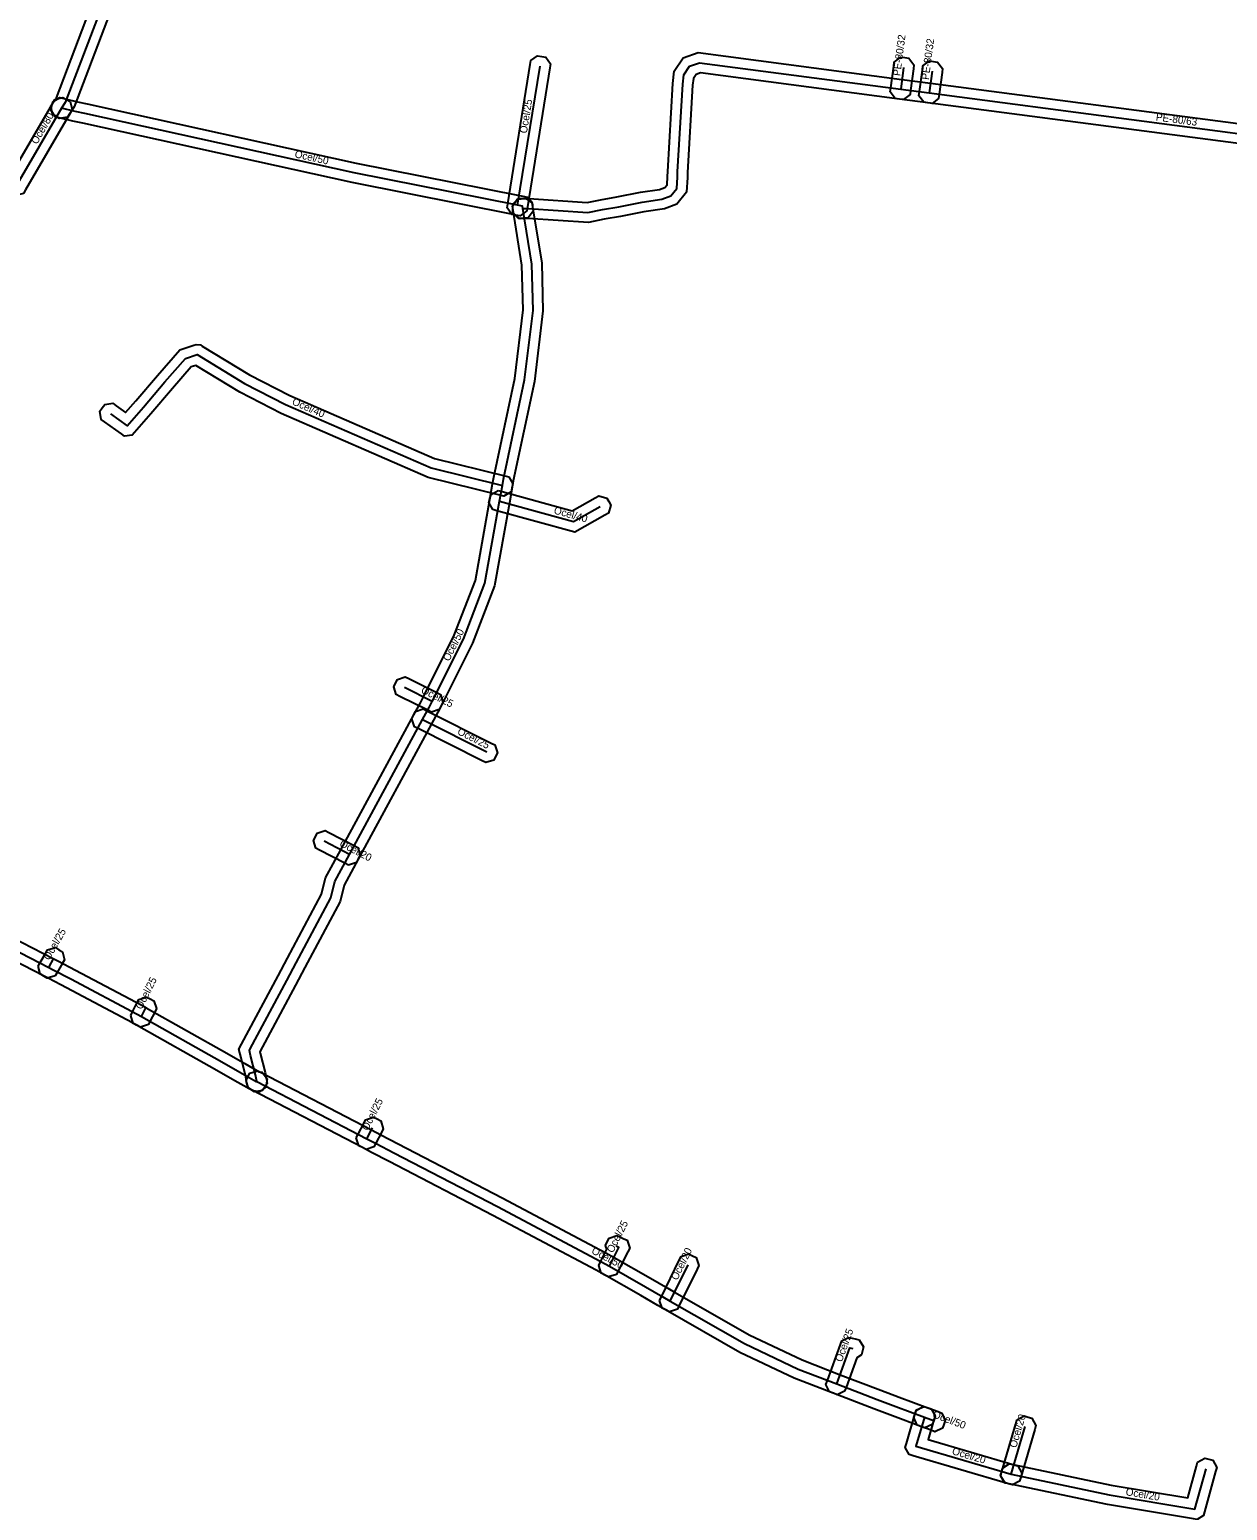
# Model space of a CAD drawing. Extents: x -569373 to -565022, y -1135090 to -1131496.
# Drawn here: x -565419.4 to -565298.7, y -1134134.8 to -1133985.7 of the extents above; entities that cross this region are included whole.
import ezdxf

# ---------------------------------------------------------------- set-up
doc = ezdxf.new("R2010")
doc.units = 0
for name, color, linetype in [('1', 7, 'Continuous'), ('24', 7, 'Continuous'), ('30', 7, 'Continuous')]:
    doc.layers.add(name, color=color, linetype=linetype)

msp = doc.modelspace()

# ---------------------------------------------------------------- linework, layer by layer
at = {"layer": '1'}
for points in [[(-565408.608, -1133977.01), (-565414.865, -1133993.461), (-565415.308, -1133994.125), (-565415.538, -1133994.47), (-565416.35, -1133994.632), (-565416.695, -1133994.402), (-565417.04, -1133994.172), (-565417.202, -1133993.36), (-565416.972, -1133993.015), (-565416.655, -1133992.539), (-565410.452, -1133976.23)], [(-565288.17, -1133998.391), (-565328.891, -1133993.041), (-565331.77, -1133992.661), (-565351.801, -1133990.033), (-565352.249, -1133990.193), (-565352.515, -1133990.581), (-565352.593, -1133991.266), (-565353.101, -1134000.048), (-565353.121, -1134000.57), (-565353.211, -1134002.05), (-565354.174, -1134003.241), (-565355.439, -1134003.714), (-565357.49, -1134004.016), (-565359.846, -1134004.483), (-565361.482, -1134004.772), (-565363.061, -1134005.097), (-565369.172, -1134004.689), (-565369.708, -1134004.68), (-565370.122, -1134004.673), (-565370.697, -1134004.076), (-565370.69, -1134003.662), (-565370.683, -1134003.248), (-565370.086, -1134002.673), (-565369.672, -1134002.68), (-565369.088, -1134002.691), (-565363.199, -1134003.083), (-565361.858, -1134002.808), (-565360.214, -1134002.517), (-565357.83, -1134002.044), (-565355.941, -1134001.766), (-565355.386, -1134001.559), (-565355.169, -1134001.29), (-565355.119, -1134000.47), (-565355.099, -1133999.952), (-565354.587, -1133991.094), (-565354.445, -1133989.859), (-565353.531, -1133988.527), (-565352.019, -1133987.987), (-565331.51, -1133990.679), (-565328.629, -1133991.059), (-565287.91, -1133996.409)], [(-565426.369, -1134074.378), (-565416.973, -1134079.21), (-565416.511, -1134079.447), (-565414.727, -1134080.364), (-565408.042, -1134083.912), (-565407.6, -1134084.158), (-565399.495, -1134088.741), (-565397.685, -1134089.781), (-565396.222, -1134090.607), (-565395.929, -1134090.648), (-565395.432, -1134091.311), (-565395.49, -1134091.721), (-565395.548, -1134092.131), (-565396.211, -1134092.628), (-565396.621, -1134092.57), (-565396.878, -1134092.533), (-565398.675, -1134091.519), (-565400.485, -1134090.479), (-565408.58, -1134085.902), (-565408.998, -1134085.668), (-565415.653, -1134082.136), (-565417.425, -1134081.227), (-565417.887, -1134080.99), (-565427.351, -1134076.122)]]:
    msp.add_lwpolyline(points, dxfattribs=at)
for points in [[(-565371.273, -1134003.609), (-565371.207, -1134003.2), (-565368.937, -1133989.19), (-565368.871, -1133988.781), (-565368.199, -1133988.297), (-565367.79, -1133988.363), (-565367.381, -1133988.429), (-565366.897, -1133989.101), (-565366.963, -1133989.51), (-565369.233, -1134003.52), (-565369.299, -1134003.929), (-565369.971, -1134004.413), (-565370.38, -1134004.347), (-565370.789, -1134004.281)], [(-565330.304, -1133989.201), (-565330.359, -1133989.611), (-565330.649, -1133991.801), (-565330.703, -1133992.212), (-565331.361, -1133992.716), (-565331.771, -1133992.661), (-565332.182, -1133992.607), (-565332.686, -1133991.949), (-565332.631, -1133991.539), (-565332.341, -1133989.349), (-565332.287, -1133988.938), (-565331.629, -1133988.434), (-565331.219, -1133988.489), (-565330.808, -1133988.543)], [(-565327.424, -1133989.592), (-565327.479, -1133990.002), (-565327.769, -1133992.182), (-565327.824, -1133992.592), (-565328.482, -1133993.096), (-565328.892, -1133993.041), (-565329.302, -1133992.986), (-565329.806, -1133992.328), (-565329.751, -1133991.918), (-565329.461, -1133989.738), (-565329.406, -1133989.328), (-565328.748, -1133988.824), (-565328.338, -1133988.879), (-565327.928, -1133988.934)], [(-565415.067, -1133993.714), (-565415.275, -1133994.072), (-565419.765, -1134001.802), (-565419.973, -1134002.16), (-565420.774, -1134002.373), (-565421.132, -1134002.165), (-565421.49, -1134001.957), (-565421.703, -1134001.156), (-565421.495, -1134000.798), (-565417.005, -1133993.068), (-565416.797, -1133992.71), (-565415.996, -1133992.497), (-565415.638, -1133992.705), (-565415.28, -1133992.913)], [(-565369.965, -1134004.727), (-565370.493, -1134004.326), (-565386.885, -1134001.079), (-565413.994, -1133995.103), (-565414.987, -1133994.884), (-565416.379, -1133994.541), (-565416.781, -1133994.442), (-565417.21, -1133993.733), (-565417.111, -1133993.331), (-565417.012, -1133992.929), (-565416.303, -1133992.5), (-565415.901, -1133992.599), (-565414.533, -1133992.936), (-565413.564, -1133993.149), (-565386.475, -1133999.121), (-565370.025, -1134002.379), (-565369.524, -1134002.479), (-565369.21, -1134002.542), (-565368.772, -1134003.008), (-565368.729, -1134003.325), (-565368.699, -1134003.545), (-565368.643, -1134003.955), (-565369.145, -1134004.615), (-565369.555, -1134004.671)], [(-565392.567, -1134081.89), (-565396.157, -1134088.592), (-565396.125, -1134088.719), (-565395.633, -1134090.685), (-565395.498, -1134091.392), (-565395.42, -1134091.799), (-565395.885, -1134092.484), (-565396.292, -1134092.562), (-565396.699, -1134092.64), (-565397.384, -1134092.175), (-565397.462, -1134091.768), (-565397.587, -1134091.115), (-565398.065, -1134089.203), (-565398.283, -1134088.329), (-565398.022, -1134087.839), (-565394.333, -1134080.95), (-565393.394, -1134079.172), (-565389.97, -1134072.729), (-565389.559, -1134071.085), (-565388.019, -1134068.244), (-565380.669, -1134054.673), (-565380.005, -1134053.454), (-565379.703, -1134052.859), (-565376.586, -1134046.656), (-565374.468, -1134041.131), (-565373.015, -1134032.975), (-565372.735, -1134031.398), (-565372.622, -1134030.741), (-565370.497, -1134020.785), (-565369.662, -1134013.892), (-565369.778, -1134009.383), (-565370.677, -1134003.84), (-565370.743, -1134003.431), (-565370.259, -1134002.759), (-565369.85, -1134002.693), (-565369.441, -1134002.627), (-565368.769, -1134003.111), (-565368.703, -1134003.52), (-565367.782, -1134009.197), (-565367.658, -1134013.988), (-565368.523, -1134021.115), (-565370.658, -1134031.119), (-565370.765, -1134031.742), (-565371.045, -1134033.325), (-565372.532, -1134041.669), (-565374.754, -1134047.464), (-565377.917, -1134053.761), (-565378.235, -1134054.386), (-565378.911, -1134055.627), (-565386.261, -1134069.196), (-565387.681, -1134071.815), (-565388.09, -1134073.451), (-565391.626, -1134080.108)], [(-565410.971, -1134023.297), (-565410.635, -1134023.539), (-565409.686, -1134024.224), (-565408.658, -1134023.037), (-565406.487, -1134020.487), (-565404.232, -1134017.904), (-565402.799, -1134017.439), (-565402.591, -1134017.371), (-565402.156, -1134017.422), (-565401.969, -1134017.536), (-565397.211, -1134020.437), (-565393.152, -1134022.516), (-565378.589, -1134028.859), (-565371.511, -1134030.599), (-565371.109, -1134030.698), (-565370.68, -1134031.407), (-565370.779, -1134031.809), (-565370.878, -1134032.211), (-565371.587, -1134032.64), (-565371.989, -1134032.541), (-565379.231, -1134030.761), (-565394.008, -1134024.324), (-565398.189, -1134022.183), (-565402.618, -1134019.483), (-565403.088, -1134019.636), (-565404.973, -1134021.793), (-565407.14, -1134024.341), (-565408.774, -1134026.225), (-565409.029, -1134026.518), (-565409.8, -1134026.608), (-565410.115, -1134026.381), (-565411.805, -1134025.161), (-565412.141, -1134024.918), (-565412.273, -1134024.101), (-565412.031, -1134023.765), (-565411.788, -1134023.429)], [(-565372.162, -1134032.075), (-565371.763, -1134032.186), (-565364.723, -1134034.136), (-565362.403, -1134032.82), (-565362.043, -1134032.616), (-565361.245, -1134032.837), (-565361.04, -1134033.197), (-565360.836, -1134033.557), (-565361.057, -1134034.355), (-565361.417, -1134034.56), (-565364.457, -1134036.284), (-565372.297, -1134034.114), (-565372.696, -1134034.003), (-565373.105, -1134033.282), (-565372.994, -1134032.883), (-565372.883, -1134032.484)], [(-565378.887, -1134054.39), (-565379.257, -1134054.204), (-565382.057, -1134052.804), (-565382.428, -1134052.619), (-565382.69, -1134051.833), (-565382.504, -1134051.463), (-565382.319, -1134051.092), (-565381.533, -1134050.83), (-565381.163, -1134051.016), (-565378.363, -1134052.416), (-565377.992, -1134052.601), (-565377.73, -1134053.387), (-565377.916, -1134053.757), (-565378.101, -1134054.128)], [(-565379.711, -1134054.07), (-565379.341, -1134054.256), (-565372.871, -1134057.506), (-565372.501, -1134057.692), (-565372.24, -1134058.479), (-565372.426, -1134058.849), (-565372.612, -1134059.219), (-565373.399, -1134059.48), (-565373.769, -1134059.294), (-565380.239, -1134056.044), (-565380.609, -1134055.858), (-565380.87, -1134055.071), (-565380.684, -1134054.701), (-565380.498, -1134054.331)], [(-565387.232, -1134069.799), (-565387.6, -1134069.608), (-565390.15, -1134068.288), (-565390.518, -1134068.097), (-565390.769, -1134067.308), (-565390.578, -1134066.94), (-565390.387, -1134066.572), (-565389.598, -1134066.321), (-565389.23, -1134066.512), (-565386.68, -1134067.832), (-565386.312, -1134068.023), (-565386.061, -1134068.812), (-565386.252, -1134069.18), (-565386.443, -1134069.548)], [(-565418.503, -1134079.96), (-565418.296, -1134079.601), (-565417.766, -1134078.681), (-565417.559, -1134078.322), (-565416.76, -1134078.107), (-565416.401, -1134078.314), (-565416.042, -1134078.521), (-565415.827, -1134079.32), (-565416.034, -1134079.679), (-565416.564, -1134080.599), (-565416.771, -1134080.958), (-565417.57, -1134081.173), (-565417.929, -1134080.966), (-565418.288, -1134080.759)], [(-565409.169, -1134084.948), (-565408.982, -1134084.579), (-565408.542, -1134083.709), (-565408.355, -1134083.339), (-565407.568, -1134083.081), (-565407.199, -1134083.268), (-565406.829, -1134083.455), (-565406.571, -1134084.242), (-565406.758, -1134084.611), (-565407.198, -1134085.481), (-565407.385, -1134085.851), (-565408.172, -1134086.109), (-565408.541, -1134085.922), (-565408.911, -1134085.735)], [(-565396.386, -1134090.502), (-565396.019, -1134090.693), (-565384.918, -1134096.463), (-565383.998, -1134096.943), (-565382.229, -1134097.863), (-565371.765, -1134103.294), (-565361.34, -1134108.823), (-565360.476, -1134109.311), (-565356.823, -1134111.402), (-565355.086, -1134112.397), (-565354.343, -1134112.822), (-565346.906, -1134117.083), (-565341.565, -1134119.621), (-565337.72, -1134121.107), (-565333.646, -1134122.675), (-565331.78, -1134123.37), (-565328.901, -1134124.443), (-565328.513, -1134124.588), (-565328.168, -1134125.341), (-565328.313, -1134125.729), (-565328.458, -1134126.117), (-565329.211, -1134126.462), (-565329.599, -1134126.317), (-565332.478, -1134125.244), (-565334.354, -1134124.545), (-565338.44, -1134122.973), (-565342.355, -1134121.459), (-565347.834, -1134118.857), (-565355.337, -1134114.558), (-565356.08, -1134114.133), (-565357.817, -1134113.138), (-565361.464, -1134111.049), (-565362.3, -1134110.577), (-565372.695, -1134105.066), (-565383.151, -1134099.637), (-565384.922, -1134098.717), (-565385.842, -1134098.237), (-565396.941, -1134092.467), (-565397.309, -1134092.276), (-565397.558, -1134091.486), (-565397.367, -1134091.119), (-565397.176, -1134090.751)], [(-565386.459, -1134097.265), (-565386.271, -1134096.896), (-565385.711, -1134095.796), (-565385.523, -1134095.427), (-565384.735, -1134095.171), (-565384.366, -1134095.359), (-565383.997, -1134095.547), (-565383.741, -1134096.335), (-565383.929, -1134096.704), (-565384.489, -1134097.804), (-565384.677, -1134098.173), (-565385.465, -1134098.429), (-565385.834, -1134098.241), (-565386.203, -1134098.053)], [(-565361.862, -1134109.727), (-565361.228, -1134108.479), (-565361.361, -1134108.099), (-565361.181, -1134107.726), (-565361.001, -1134107.353), (-565360.219, -1134107.079), (-565359.846, -1134107.259), (-565359.576, -1134107.389), (-565359.197, -1134107.571), (-565359.063, -1134107.97), (-565358.928, -1134108.368), (-565359.118, -1134108.743), (-565360.078, -1134110.633), (-565360.266, -1134111.002), (-565361.054, -1134111.259), (-565361.423, -1134111.072), (-565361.792, -1134110.884), (-565362.049, -1134110.096)], [(-565355.92, -1134113.621), (-565355.737, -1134113.249), (-565353.937, -1134109.589), (-565353.754, -1134109.217), (-565352.971, -1134108.95), (-565352.599, -1134109.133), (-565352.227, -1134109.316), (-565351.96, -1134110.099), (-565352.143, -1134110.471), (-565353.943, -1134114.131), (-565354.126, -1134114.503), (-565354.909, -1134114.77), (-565355.281, -1134114.587), (-565355.653, -1134114.404)], [(-565335.595, -1134119.118), (-565336.055, -1134119.398), (-565337.14, -1134122.382), (-565337.282, -1134122.771), (-565338.033, -1134123.122), (-565338.422, -1134122.98), (-565338.811, -1134122.838), (-565339.162, -1134122.087), (-565339.02, -1134121.698), (-565337.7, -1134118.068), (-565337.569, -1134117.709), (-565336.896, -1134117.348), (-565336.525, -1134117.438), (-565336.235, -1134117.508), (-565335.832, -1134117.605), (-565335.401, -1134118.312), (-565335.498, -1134118.715)], [(-565328.174, -1134125.264), (-565328.29, -1134125.662), (-565328.869, -1134127.632), (-565320.228, -1134130.171), (-565319.831, -1134130.287), (-565319.434, -1134131.014), (-565319.551, -1134131.412), (-565319.667, -1134131.809), (-565320.394, -1134132.206), (-565320.792, -1134132.089), (-565330.392, -1134129.269), (-565330.789, -1134129.153), (-565331.186, -1134128.426), (-565331.07, -1134128.028), (-565330.21, -1134125.098), (-565330.093, -1134124.701), (-565329.366, -1134124.304), (-565328.968, -1134124.42), (-565328.571, -1134124.537)], [(-565329.289, -1134124.298), (-565328.901, -1134124.443), (-565327.881, -1134124.823), (-565327.493, -1134124.968), (-565327.148, -1134125.721), (-565327.293, -1134126.109), (-565327.438, -1134126.497), (-565328.191, -1134126.842), (-565328.579, -1134126.697), (-565329.599, -1134126.317), (-565329.987, -1134126.172), (-565330.332, -1134125.419), (-565330.187, -1134125.031), (-565330.042, -1134124.643)], [(-565321.586, -1134131.246), (-565321.469, -1134130.848), (-565320.059, -1134126.048), (-565319.943, -1134125.651), (-565319.216, -1134125.254), (-565318.818, -1134125.371), (-565318.421, -1134125.487), (-565318.024, -1134126.214), (-565318.141, -1134126.612), (-565319.551, -1134131.412), (-565319.667, -1134131.809), (-565320.394, -1134132.206), (-565320.792, -1134132.089), (-565321.189, -1134131.973)], [(-565320.71, -1134130.066), (-565320.305, -1134130.151), (-565310.456, -1134132.217), (-565302.734, -1134133.496), (-565301.854, -1134130.313), (-565301.743, -1134129.914), (-565301.022, -1134129.506), (-565300.623, -1134129.616), (-565300.224, -1134129.727), (-565299.816, -1134130.448), (-565299.926, -1134130.847), (-565301.046, -1134134.897), (-565301.148, -1134135.267), (-565301.795, -1134135.68), (-565302.173, -1134135.617), (-565310.824, -1134134.183), (-565320.715, -1134132.109), (-565321.121, -1134132.024), (-565321.574, -1134131.33), (-565321.489, -1134130.925), (-565321.404, -1134130.519)]]:
    msp.add_lwpolyline(points, close=True, dxfattribs=at)
at = {"layer": '24'}
for points in [[(-565278.88, -1133958.49), (-565301.52, -1133954.54), (-565323.71, -1133950.73), (-565324.51, -1133950.59), (-565329.461, -1133949.709), (-565341.87, -1133947.5), (-565352.97, -1133945.09), (-565353.3, -1133945.02), (-565361.19, -1133943.29), (-565363.14, -1133942.86), (-565372.05, -1133941.46), (-565380.96, -1133940.06), (-565381.81, -1133939.93), (-565391.89, -1133949.34), (-565397.23, -1133956.72), (-565398.344, -1133958.378), (-565407.08, -1133971.38), (-565409.53, -1133976.62), (-565415.76, -1133993), (-565416.14, -1133993.57)], [(-565369.69, -1134003.68), (-565369.13, -1134003.69), (-565363.13, -1134004.09), (-565361.67, -1134003.79), (-565360.03, -1134003.5), (-565357.66, -1134003.03), (-565355.69, -1134002.74), (-565354.78, -1134002.4), (-565354.19, -1134001.67), (-565354.12, -1134000.52), (-565354.1, -1134000), (-565353.59, -1133991.18), (-565353.48, -1133990.22), (-565352.89, -1133989.36), (-565351.91, -1133989.01), (-565331.64, -1133991.67), (-565328.76, -1133992.05), (-565288.04, -1133997.4)], [(-565370.22, -1134003.36), (-565367.95, -1133989.35)], [(-565331.35, -1133989.48), (-565331.64, -1133991.67)], [(-565328.47, -1133989.87), (-565328.76, -1133992.05)], [(-565416.14, -1133993.57), (-565420.63, -1134001.3)], [(-565369.69, -1134003.68), (-565369.72, -1134003.46), (-565370.22, -1134003.36), (-565386.68, -1134000.1), (-565413.779, -1133994.126), (-565414.76, -1133993.91), (-565416.14, -1133993.57)], [(-565396.48, -1134091.58), (-565396.61, -1134090.9), (-565397.095, -1134088.961), (-565397.22, -1134088.46), (-565397.14, -1134088.31), (-565393.45, -1134081.42), (-565392.51, -1134079.64), (-565389.03, -1134073.09), (-565388.62, -1134071.45), (-565387.14, -1134068.72), (-565379.79, -1134055.15), (-565379.12, -1134053.92), (-565378.81, -1134053.31), (-565375.67, -1134047.06), (-565373.5, -1134041.4), (-565372.03, -1134033.15), (-565371.75, -1134031.57), (-565371.64, -1134030.93), (-565369.51, -1134020.95), (-565368.66, -1134013.94), (-565368.78, -1134009.29), (-565369.69, -1134003.68)], [(-565411.22, -1134024.35), (-565409.53, -1134025.57), (-565407.899, -1134023.689), (-565405.73, -1134021.14), (-565403.66, -1134018.77), (-565402.49, -1134018.39), (-565397.7, -1134021.31), (-565393.58, -1134023.42), (-565378.91, -1134029.81), (-565371.75, -1134031.57)], [(-565372.03, -1134033.15), (-565364.59, -1134035.21), (-565361.91, -1134033.69)], [(-565378.81, -1134053.31), (-565381.61, -1134051.91)], [(-565379.79, -1134055.15), (-565373.32, -1134058.4)], [(-565387.14, -1134068.72), (-565389.69, -1134067.4)], [(-565426.86, -1134075.25), (-565417.43, -1134080.1), (-565416.968, -1134080.337), (-565415.19, -1134081.25), (-565408.52, -1134084.79), (-565408.09, -1134085.03), (-565399.99, -1134089.61), (-565398.18, -1134090.65), (-565396.55, -1134091.57), (-565396.48, -1134091.58)], [(-565417.43, -1134080.1), (-565416.9, -1134079.18)], [(-565408.09, -1134085.03), (-565407.65, -1134084.16)], [(-565396.48, -1134091.58), (-565385.38, -1134097.35), (-565384.46, -1134097.83), (-565382.69, -1134098.75), (-565372.23, -1134104.18), (-565361.82, -1134109.7), (-565360.97, -1134110.18), (-565357.32, -1134112.27), (-565355.583, -1134113.265), (-565354.84, -1134113.69), (-565347.37, -1134117.97), (-565341.96, -1134120.54), (-565338.08, -1134122.04), (-565334, -1134123.61), (-565332.129, -1134124.307), (-565329.25, -1134125.38)], [(-565385.38, -1134097.35), (-565384.82, -1134096.25)], [(-565360.97, -1134110.18), (-565360.01, -1134108.29), (-565360.28, -1134108.16)], [(-565354.84, -1134113.69), (-565353.04, -1134110.03)], [(-565338.08, -1134122.04), (-565336.76, -1134118.41), (-565336.47, -1134118.48)], [(-565329.25, -1134125.38), (-565330.11, -1134128.31), (-565320.51, -1134131.13)], [(-565329.25, -1134125.38), (-565328.23, -1134125.76)], [(-565320.51, -1134131.13), (-565319.1, -1134126.33)], [(-565320.51, -1134131.13), (-565310.64, -1134133.2), (-565302.01, -1134134.63), (-565300.89, -1134130.58)]]:
    msp.add_lwpolyline(points, dxfattribs=at)

# ---------------------------------------------------------------- texts
at = {"layer": '30'}
for s, rotation, p in [('PE-80/32', 82.45677, (-565331.695, -1133990.375)), ('PE-80/32', 82.42257, (-565328.815, -1133990.76)), ('Ocel/25', 80.79651, (-565369.285, -1133996.155)), ('Ocel/80', 59.84967, (-565418.61, -1133997.278)), ('PE-80/63', 352.51506, (-565305.981, -1133994.817)), ('Ocel/50', 347.56794, (-565392.712, -1133998.526)), ('Ocel/40', 336.46289, (-565392.996, -1134023.387)), ('Ocel/40', 344.52356, (-565366.625, -1134034.391)), ('Ocel/50', 63.32505, (-565377.112, -1134049.333)), ('Ocel/25', 333.43495, (-565380.01, -1134052.41)), ('Ocel/25', 333.32878, (-565376.355, -1134056.575)), ('Ocel/20', 332.63179, (-565388.215, -1134067.86)), ('Ocel/25', 60.05432, (-565417.365, -1134079.44)), ('Ocel/25', 63.17213, (-565408.07, -1134084.395)), ('Ocel/25', 63.01977, (-565385.3, -1134096.6)), ('Ocel/25', 63.07232, (-565360.622, -1134108.901)), ('Ocel/50', 332.06481, (-565362.844, -1134108.851)), ('Ocel/20', 63.81189, (-565354.14, -1134111.66)), ('Ocel/25', 70.01689, (-565337.569, -1134119.885)), ('Ocel/50', 339.56717, (-565328.493, -1134125.387)), ('Ocel/20', 73.62985, (-565320.005, -1134128.53)), ('Ocel/20', 343.62985, (-565326.527, -1134129.104)), ('Ocel/20', 350.59152, (-565309.027, -1134133.234))]:
    msp.add_text(s, height=0.75, rotation=rotation, dxfattribs=at).set_placement(p)

doc.saveas('drawing.dxf')
